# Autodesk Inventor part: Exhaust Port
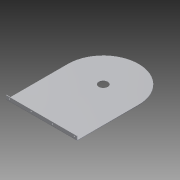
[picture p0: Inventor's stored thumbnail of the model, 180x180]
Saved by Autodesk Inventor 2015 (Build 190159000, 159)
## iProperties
Created: 2006-05
Part Number: Exhaust Port
Document SubType Name: Sheet Metal
Designer: Autodesk, Inc.
Density: 2.71 g/cm^3
Material: Aluminum-6061
Mass: 1724.85 g
Surface Area: 4237.72 cm^2
Volume: 636.476 cm^3
Sheet Metal Rule: Default
Appearance: Aluminum - Flat
Author: Autodesk, Inc.
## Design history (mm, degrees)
derived "MainGeom.ipt"
  sketch "Sketch1"
    geometry: L1 (0, 300)-(-300, 300) reference; L2 (-300, 0)-(-300, 300) reference; L3 (-200, 0)-(-200, -350) reference; L4 (-200, -350)-(200, -350) reference; L5 (200, -350)-(200, 0) reference; C1 r 100 at (0, 0) reference; C2 r 25.4 at (0, 0); A1 r 300 centre (0, 0) between (0, 300) and (-300, 0) reference; A2 r 200 centre (0, 0) between (200, 0) and (-200, 0) reference; 1 further point
    constraints: 1 centre point, 1 coincident
    dimensions: "d30" = 50.8 diameter of C2
node "Face2"
sketch "Sketch8"
  geometry: C1 r 25.4 at (0, 0) reference
cut "Cut1" sketch "Sketch8" dims "d32" = 3.048 (= Thickness), "d33" = 0
node "Flange2"
hole "Hole1" diameter "d45" = 6.7564; stored, may be unused: countersink angle "d49" = 82 deg, drill point angle "d51" = 118 deg; dims "d43" = 9.525, "d44" = 19.05, "d46" = 12.7, "d47" = 11.1252, "d48" = 6.35, "d50" = 3.048 (= Thickness)
pattern_linear "Rectangular Pattern1" dims "d54" = 121.92
body "Solid1"
face "Plate3" dims "Thickness" = 3.048
sketch "Sketch9"
  geometry: L1 through (200, 0) direction (-1, 0); L2 through (0, -12.7) direction (0, -1); L3 (0, -25.4)-(400, -25.4); L4 (400, -25.4)-(400, 0)
  constraints: 6 end point, 1 horizontal, 1 perpendicular, 1 vertical
face "Plate4" dims "d34" = 3.048 (= BendReliefWidth), "d35" = 1.524 (= BendReliefDepth), "d36" = 6.096 (= MinimumRemnant), "d37" = 3.048 (= BendRadius), "d38" = 25.4, "d39" = 90 deg, "d40" = 3.048 (= BendRadius), "d41" = 12.192 (= CornerReliefSize), "d42" = 3.048 (= Thickness), "d55" = 3.048 (= JacobiRadiusSize), "SeamGap" = 0.01, "Thickness" = 3.048
bend "Bend2" dims "d34" = 3.048 (= BendReliefWidth), "d35" = 1.524 (= BendReliefDepth), "d36" = 6.096 (= MinimumRemnant), "d37" = 3.048 (= BendRadius), "d38" = 25.4, "d39" = 90 deg, "d40" = 3.048 (= BendRadius), "SeamGap" = 0.01, "Thickness" = 3.048
feature "Corner2" dims "d38" = 25.4, "d39" = 90 deg, "d41" = 12.192 (= CornerReliefSize), "d42" = 3.048 (= Thickness), "d55" = 3.048 (= JacobiRadiusSize)
other parameters: "t" = 3 [user parameter], "BendRadius" = 3.048 (= Thickness), "BendReliefWidth" = 3.048 (= Thickness), "BendReliefDepth" = 1.524 (= 0.5 x Thickness), "CornerReliefSize" = 12.192 (= 4 x Thickness), "MinimumRemnant" = 6.096 (= 2 x Thickness), "TransitionRadius" = 3.048 (= BendRadius), "JacobiRadiusSize" = 3.048 (= Thickness), "d20" = 3.048 (= BendRadius), "d31" = 3.048 (= BendRadius), "GapSize" = 3.048 (= Thickness)
